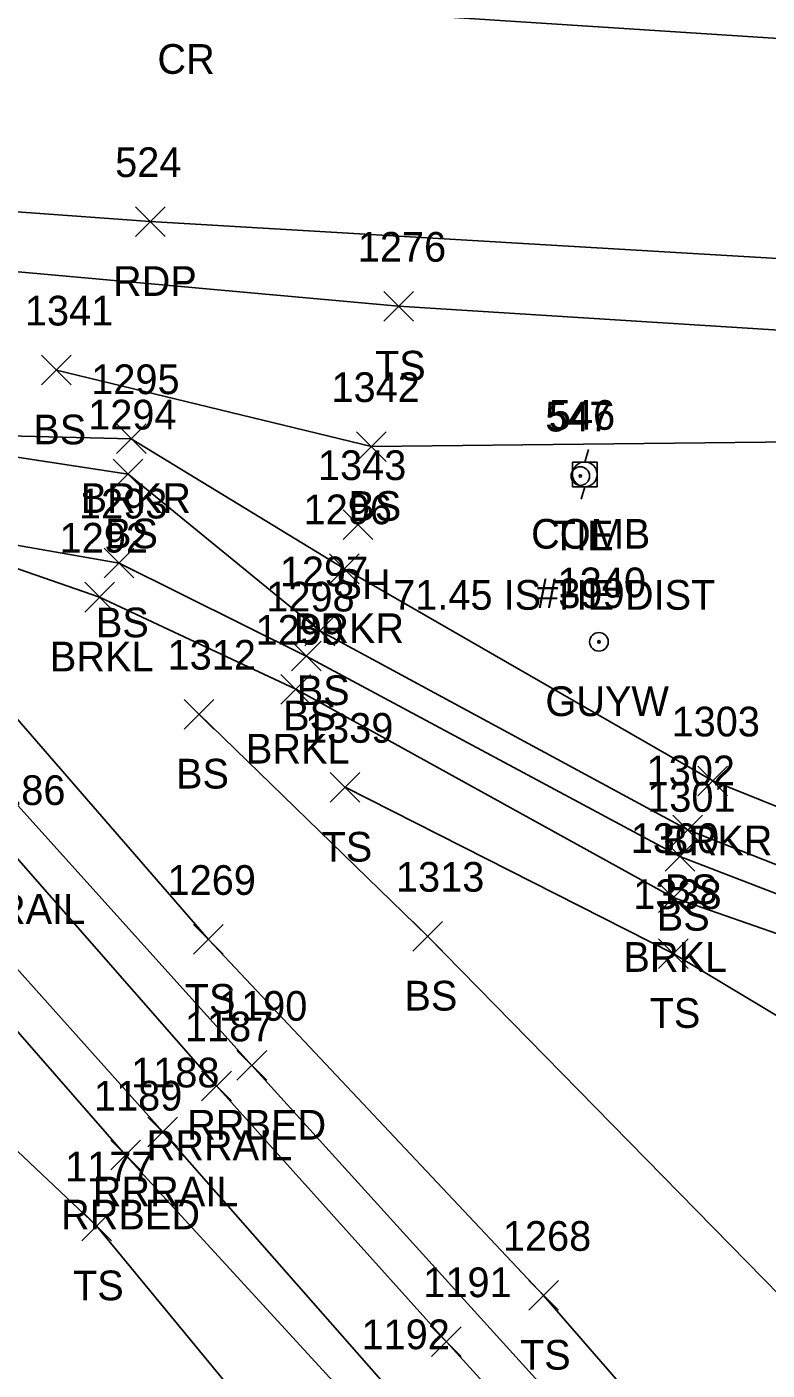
# Model space of a CAD drawing. Extents: x 1679360 to 1685861, y 903420 to 905946.
# Drawn here: x 1679883.3 to 1679933.1, y 903931.8 to 904022.2 of the extents above; entities that cross this region are included whole.
import ezdxf

# ---------------------------------------------------------------- set-up
doc = ezdxf.new("R2010")
doc.units = 0
for name, color, linetype in [('C_A', 7, 'Continuous'), ('C_C', 7, 'Continuous'), ('C_I', 7, 'Continuous'), ('CBP', 7, 'Continuous'), ('L_A', 7, 'Continuous'), ('L_I', 7, 'Continuous'), ('L_TIC', 7, 'Continuous'), ('LAWE', 7, 'Continuous'), ('LELB', 7, 'Continuous'), ('P_A', 7, 'Continuous'), ('P_I', 7, 'Continuous'), ('P_TIC', 7, 'Continuous'), ('PET', 7, 'Continuous'), ('PRC', 7, 'Continuous'), ('R_A', 7, 'Continuous'), ('R_I', 7, 'Continuous'), ('R_TIC', 7, 'Continuous'), ('RR', 7, 'Continuous'), ('RRB', 7, 'Continuous'), ('U_A', 7, 'Continuous'), ('U_C', 7, 'Continuous'), ('U_I', 7, 'Continuous'), ('UP', 7, 'Continuous'), ('UPGW', 7, 'Continuous')]:
    doc.layers.add(name, color=color, linetype=linetype)

msp = doc.modelspace()

# ---------------------------------------------------------------- linework, layer by layer
at = {"layer": 'CBP'}
for radius in [0.625, 0.0833]:
    msp.add_circle((1679920.557, 903991.966), radius, dxfattribs=at)
at = {"layer": 'L_TIC'}
for points in [[(1679907.317, 904002.394), (1679909.317, 904004.394)], [(1679909.317, 904002.394), (1679907.317, 904004.394)], [(1679884.274, 903998.1), (1679886.274, 904000.1)], [(1679886.274, 903998.1), (1679884.274, 904000.1)], [(1679889.312, 903993.48), (1679891.312, 903995.48)], [(1679891.312, 903993.48), (1679889.312, 903995.48)], [(1679905.49, 903992.95), (1679907.49, 903994.95)], [(1679907.49, 903992.95), (1679905.49, 903994.95)], [(1679889.104, 903991.101), (1679891.104, 903993.101)], [(1679891.104, 903991.101), (1679889.104, 903993.101)], [(1679904.582, 903987.695), (1679906.582, 903989.695)], [(1679906.582, 903987.695), (1679904.582, 903989.695)], [(1679888.488, 903985.11), (1679890.488, 903987.11)], [(1679890.488, 903985.11), (1679888.488, 903987.11)], [(1679903.668, 903984.721), (1679905.668, 903986.721)], [(1679905.668, 903984.721), (1679903.668, 903986.721)], [(1679887.185, 903982.814), (1679889.185, 903984.814)], [(1679889.185, 903982.814), (1679887.185, 903984.814)], [(1679902.013, 903980.546), (1679904.013, 903982.546)], [(1679904.013, 903980.546), (1679902.013, 903982.546)], [(1679901.1, 903978.853), (1679903.1, 903980.853)], [(1679903.1, 903978.853), (1679901.1, 903980.853)], [(1679900.387, 903976.613), (1679902.387, 903978.613)], [(1679902.387, 903976.613), (1679900.387, 903978.613)], [(1679893.886, 903974.933), (1679895.886, 903976.933)], [(1679895.886, 903974.933), (1679893.886, 903976.933)], [(1679928.473, 903970.44), (1679930.473, 903972.44)], [(1679930.473, 903970.44), (1679928.473, 903972.44)], [(1679903.717, 903970.013), (1679905.717, 903972.013)], [(1679905.717, 903970.013), (1679903.717, 903972.013)], [(1679926.794, 903967.15), (1679928.794, 903969.15)], [(1679928.794, 903967.15), (1679926.794, 903969.15)], [(1679926.266, 903965.366), (1679928.266, 903967.366)], [(1679928.266, 903965.366), (1679926.266, 903967.366)], [(1679925.813, 903962.593), (1679927.813, 903964.593)], [(1679927.813, 903962.593), (1679925.813, 903964.593)], [(1679894.506, 903959.774), (1679896.506, 903961.774)], [(1679896.506, 903959.774), (1679894.506, 903961.774)], [(1679909.268, 903959.988), (1679911.268, 903961.988)], [(1679911.268, 903959.988), (1679909.268, 903961.988)], [(1679925.815, 903958.822), (1679927.815, 903960.822)], [(1679927.815, 903958.822), (1679925.815, 903960.822)], [(1679886.98, 903940.486), (1679888.98, 903942.486)], [(1679888.98, 903940.486), (1679886.98, 903942.486)], [(1679917.081, 903935.814), (1679919.081, 903937.814)], [(1679919.081, 903935.814), (1679917.081, 903937.814)]]:
    msp.add_lwpolyline(points, dxfattribs=at)
at = {"layer": 'LAWE'}
for points in [[(1679871.805, 903994.911), (1679890.312, 903994.48), (1679904.668, 903985.721), (1679929.473, 903971.44), (1679948.499, 903963.819), (1679973.974, 903954.719)], [(1679877.864, 903987.384), (1679888.185, 903983.814), (1679901.387, 903977.613), (1679926.813, 903963.593), (1679943.836, 903957.668), (1679971.853, 903947.012)]]:
    msp.add_lwpolyline(points, dxfattribs=at)
at = {"layer": 'LELB'}
for points in [[(1679868.123, 903992.581), (1679867.449, 903997.953), (1679872.232, 904006.644), (1679908.317, 904003.394), (1679946.047, 904001.015), (1679984.241, 903997.59), (1680029.094, 903994.379), (1680069.55, 903991.418), (1680115.048, 903987.488), (1680162.583, 903984.342), (1680207.954, 903980.989)], [(1679885.274, 903999.1), (1679906.49, 903993.95), (1679939.137, 903994.324), (1679976.552, 903986.198), (1680022.714, 903980.953), (1680073.567, 903979.03), (1680122.893, 903976.605), (1680170.406, 903973.975), (1680212.604, 903970.941)], [(1679872.593, 903994.19), (1679871.887, 903994.882), (1679890.104, 903992.101), (1679903.013, 903981.546), (1679927.794, 903968.15), (1679945.991, 903961.002), (1679973.216, 903951.744)], [(1679877.317, 903988.235), (1679889.488, 903986.11), (1679902.1, 903979.853), (1679927.266, 903966.366), (1679945.306, 903959.401), (1679972.678, 903949.632)], [(1680042.476, 903807.682), (1680020.066, 903831.145), (1679994.569, 903854.854), (1679973.518, 903877.192), (1679947.493, 903902.981), (1679918.081, 903936.814), (1679895.506, 903960.774), (1679875.104, 903984.265)], [(1679894.886, 903975.933), (1679910.268, 903960.988), (1679935.154, 903935.627), (1679969.342, 903902.547), (1679995.856, 903870.356), (1680023.142, 903838.663), (1680052.096, 903810.883)], [(1680077.44, 903833.796), (1680042.598, 903866.063), (1680014.369, 903895.635), (1679983.06, 903925.509), (1679955.892, 903942.385), (1679926.815, 903959.822), (1679904.717, 903971.013)], [(1680027.001, 903796.796), (1680001.4, 903822.237), (1679984.382, 903839.7), (1679957.185, 903867.741), (1679928.197, 903894.121), (1679909.106, 903915.884), (1679887.98, 903941.486), (1679868.316, 903960.054)]]:
    msp.add_lwpolyline(points, dxfattribs=at)
at = {"layer": 'P_TIC'}
for points in [[(1679890.591, 904008.092), (1679892.591, 904010.092)], [(1679892.591, 904008.092), (1679890.591, 904010.092)]]:
    msp.add_lwpolyline(points, dxfattribs=at)
at = {"layer": 'PET'}
msp.add_lwpolyline([(1680207.925, 903985.129), (1680151.693, 903989.51), (1680097.956, 903992.814), (1680047.952, 903996.664), (1679996.841, 904001.699), (1679939.177, 904006.29), (1679891.591, 904009.092), (1679852.589, 904011.923), (1679848.664, 904011.26), (1679842.11, 904010.48), (1679836.311, 904011.491), (1679826.762, 904014.608), (1679807.928, 904016.053), (1679789.628, 904016.53)], dxfattribs=at)
at = {"layer": 'PRC'}
msp.add_lwpolyline([(1680209.647, 904002.035), (1680152.969, 904005.778), (1680100.293, 904009.571), (1680049.215, 904012.915), (1679999.459, 904016.395), (1679940.504, 904020.993), (1679893.641, 904024.04), (1679847.029, 904027.439), (1679827.532, 904028.695), (1679808.607, 904029.86), (1679757.066, 904033.501), (1679707.387, 904036.979), (1679666.219, 904040.385), (1679623.034, 904043.249), (1679581.591, 904046.254), (1679534.875, 904049.67), (1679494.868, 904052.553), (1679467.343, 904054.684)], dxfattribs=at)
at = {"layer": 'R_TIC'}
for points in [[(1679897.433, 903951.3), (1679899.433, 903953.3)], [(1679899.433, 903951.3), (1679897.433, 903953.3)], [(1679895.054, 903949.914), (1679897.054, 903951.914)], [(1679897.054, 903949.914), (1679895.054, 903951.914)], [(1679891.43, 903946.813), (1679893.43, 903948.813)], [(1679893.43, 903946.813), (1679891.43, 903948.813)], [(1679888.935, 903945.255), (1679890.935, 903947.255)], [(1679890.935, 903945.255), (1679888.935, 903947.255)], [(1679910.539, 903932.695), (1679912.539, 903934.695)], [(1679912.539, 903932.695), (1679910.539, 903934.695)]]:
    msp.add_lwpolyline(points, dxfattribs=at)
at = {"layer": 'RR'}
for points in [[(1679824.636, 904028.723), (1679837.335, 904012.385), (1679861.93, 903982.575), (1679878.201, 903963.702), (1679892.43, 903947.813), (1679907.949, 903930.191), (1679922.381, 903914.406), (1679937.847, 903897.677), (1679952.054, 903882.523), (1679968.97, 903864.985), (1679984.514, 903848.778), (1680002.835, 903830.071), (1680018.619, 903814.033), (1680033.052, 903799.461), (1680047.501, 903784.671), (1680062.832, 903769.48), (1680079.575, 903752.46), (1680095.318, 903736.478)], [(1679831.29, 904028.454), (1679844.096, 904012.062), (1679865.832, 903985.593), (1679882.113, 903966.823), (1679896.054, 903950.914), (1679911.539, 903933.695), (1679925.868, 903917.928), (1679941.581, 903900.906), (1679955.487, 903886.236), (1679972.276, 903868.599), (1679988.045, 903852.199), (1680006.222, 903833.297), (1680022.216, 903817.371), (1680036.492, 903802.967), (1680051.111, 903788.214), (1680066.385, 903772.907), (1680082.823, 903756.115), (1680099.284, 903739.482)]]:
    msp.add_lwpolyline(points, dxfattribs=at)
at = {"layer": 'RRB'}
for points in [[(1679852.795, 904005.562), (1679867.147, 903987.017), (1679898.433, 903952.3), (1679928.167, 903919.501), (1679957.856, 903886.729), (1679990.498, 903854.155), (1680024.928, 903818.736), (1680038.518, 903804.879)], [(1679840.738, 904004.217), (1679860.452, 903979.987), (1679889.935, 903946.255), (1679920.699, 903912.732), (1679950.152, 903880.788), (1679982.316, 903846.881), (1680017.14, 903812.199), (1680030.44, 903798.069)]]:
    msp.add_lwpolyline(points, dxfattribs=at)
at = {"layer": 'UP'}
for p, q in [((1679921.107, 903993.744), (1679920.857, 903992.911)), ((1679920.024, 903991.245), (1679920.024, 903992.911)), ((1679920.024, 903992.911), (1679921.691, 903992.911)), ((1679921.691, 903992.911), (1679921.691, 903991.245)), ((1679920.857, 903992.078), (1679920.857, 903992.078)), ((1679921.691, 903991.245), (1679920.024, 903991.245)), ((1679920.607, 903990.411), (1679920.857, 903991.245))]:
    msp.add_line(p, q, dxfattribs=at)
msp.add_circle((1679920.857, 903992.078), 0.833, dxfattribs=at)
at = {"layer": 'UPGW'}
for radius in [0.625, 0.0833]:
    msp.add_circle((1679921.809, 903980.808), radius, dxfattribs=at)

# ---------------------------------------------------------------- texts
at = {"layer": 'C_A'}
msp.add_text('TIE', height=2, dxfattribs=at).set_placement((1679918.636, 903986.966))
at = {"layer": 'C_C'}
msp.add_text('71.45 IS TIE DIST', height=2, dxfattribs=at).set_placement((1679907.951, 903982.966))
at = {"layer": 'C_I'}
msp.add_text('547', height=2, dxfattribs=at).set_placement((1679918.195, 903994.966))
at = {"layer": 'L_A'}
for s, p in [('TS', (1679906.727, 903998.394)), ('BS', (1679883.715, 903994.1)), ('BRKR', (1679886.902, 903989.48)), ('BS', (1679904.931, 903988.95)), ('BS', (1679888.545, 903987.101)), ('SH', (1679904.07, 903983.695)), ('BS', (1679887.929, 903981.11)), ('BRKR', (1679901.258, 903980.721)), ('BRKL', (1679884.831, 903978.814)), ('BS', (1679901.454, 903976.546)), ('BS', (1679900.541, 903974.853)), ('BRKL', (1679898.032, 903972.613)), ('BS', (1679893.327, 903970.933)), ('TS', (1679903.126, 903966.013)), ('BRKR', (1679926.063, 903966.44)), ('BS', (1679926.235, 903963.15)), ('BS', (1679925.707, 903961.366)), ('BRKL', (1679923.459, 903958.593)), ('BS', (1679908.709, 903955.988)), ('TS', (1679893.916, 903955.774)), ('TS', (1679925.224, 903954.822)), ('TS', (1679886.39, 903936.486)), ('TS', (1679916.491, 903931.814))]:
    msp.add_text(s, height=2, dxfattribs=at).set_placement(p)
at = {"layer": 'L_I'}
for s, p in [('1276', (1679905.569, 904006.394)), ('1341', (1679883.148, 904002.1)), ('1295', (1679887.619, 903997.48)), ('1342', (1679903.797, 903996.95)), ('1294', (1679887.411, 903995.101)), ('1343', (1679902.889, 903991.695)), ('1293', (1679886.795, 903989.11)), ('1296', (1679901.92, 903988.721)), ('1292', (1679885.492, 903986.814)), ('1297', (1679900.32, 903984.546)), ('1298', (1679899.407, 903982.853)), ('1299', (1679898.686, 903980.613)), ('1312', (1679892.76, 903978.933)), ('1339', (1679902.016, 903974.013)), ('1303', (1679926.701, 903974.44)), ('1302', (1679925.022, 903971.15)), ('1301', (1679925.061, 903969.366)), ('1300', (1679923.955, 903966.593)), ('1269', (1679892.758, 903963.774)), ('1313', (1679908.142, 903963.988)), ('1338', (1679924.122, 903962.822)), ('1177', (1679885.854, 903944.486)), ('1268', (1679915.341, 903939.814))]:
    msp.add_text(s, height=2, dxfattribs=at).set_placement(p)
at = {"layer": 'P_A'}
for s, p in [('CR', (1679892.074, 904019.04)), ('RDP', (1679889.079, 904004.092))]:
    msp.add_text(s, height=2, dxfattribs=at).set_placement(p)
at = {"layer": 'P_I'}
msp.add_text('524', height=2, dxfattribs=at).set_placement((1679889.228, 904012.092))
at = {"layer": 'R_A'}
for s, p in [('RRRAIL', (1679877.405, 903961.823)), ('RRBED', (1679894.079, 903947.3)), ('RRRAIL', (1679891.345, 903945.914)), ('RRRAIL', (1679887.721, 903942.813)), ('RRBED', (1679885.581, 903941.255))]:
    msp.add_text(s, height=2, dxfattribs=at).set_placement(p)
at = {"layer": 'R_I'}
for s, p in [('1186', (1679879.932, 903969.823)), ('1190', (1679896.221, 903955.3)), ('1187', (1679893.928, 903953.914)), ('1188', (1679890.304, 903950.813)), ('1189', (1679887.801, 903949.255)), ('1191', (1679909.98, 903936.695)), ('1192', (1679905.823, 903933.191))]:
    msp.add_text(s, height=2, dxfattribs=at).set_placement(p)
at = {"layer": 'U_A'}
for s, p in [('COMB', (1679917.243, 903987.078)), ('GUYW', (1679918.203, 903975.808))]:
    msp.add_text(s, height=2, dxfattribs=at).set_placement(p)
at = {"layer": 'U_C'}
msp.add_text('#399', height=2, dxfattribs=at).set_placement((1679917.59, 903983.078))
at = {"layer": 'U_I'}
for s, p in [('546', (1679918.44, 903995.078)), ('1340', (1679919.029, 903983.808))]:
    msp.add_text(s, height=2, dxfattribs=at).set_placement(p)

doc.saveas('drawing.dxf')
